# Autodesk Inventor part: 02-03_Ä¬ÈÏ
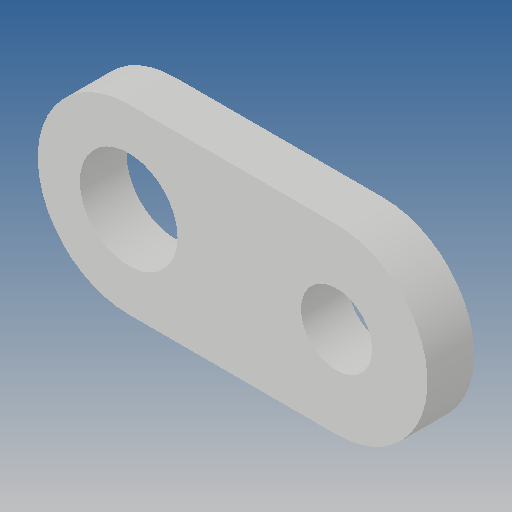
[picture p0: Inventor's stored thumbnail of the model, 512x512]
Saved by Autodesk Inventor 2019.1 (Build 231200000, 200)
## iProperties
Created: 2010-06
Part Number: 02-03_Ä¬ÈÏ
Material: Ogólny
Document SubType Name: Modeling
Designer: CADENGINEERING4
Density: 1 g/cm^3
Appearance: Domyślna
Author: CADENGINEERING4
Revision Number: ÈÎºÎ
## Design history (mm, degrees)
feature "NONE"
node "Bryła1"
